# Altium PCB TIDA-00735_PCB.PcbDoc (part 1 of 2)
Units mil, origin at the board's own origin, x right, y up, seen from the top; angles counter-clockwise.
Board outline 1000 x 2200 mil, 2 copper layers (Top Layer, Bottom Layer), stack 62 mil thick; 69 components, 59 nets, 244 pads, 158 vias.
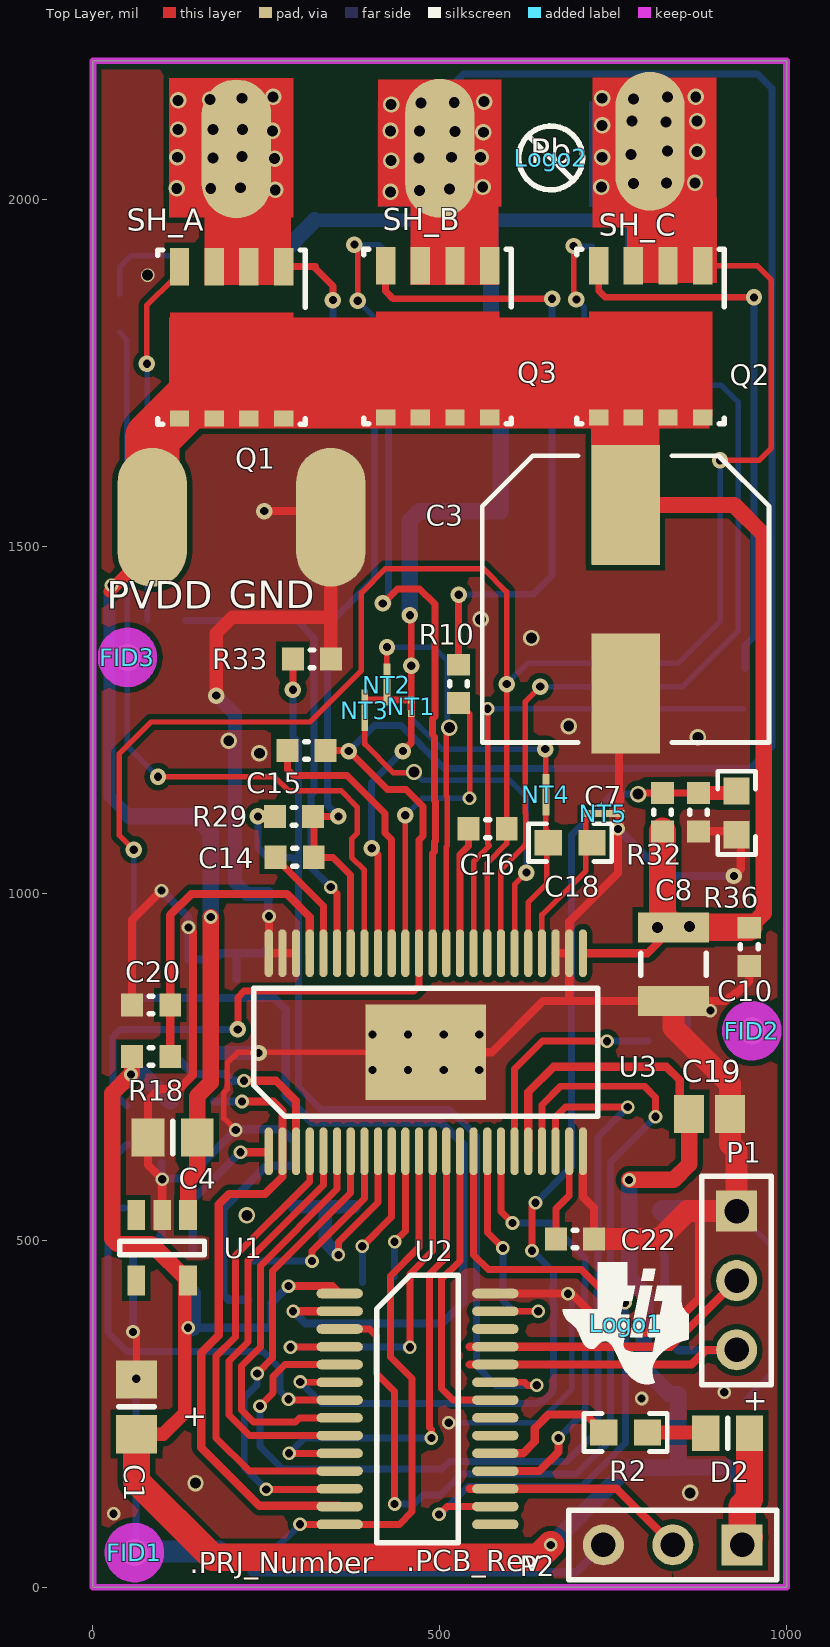
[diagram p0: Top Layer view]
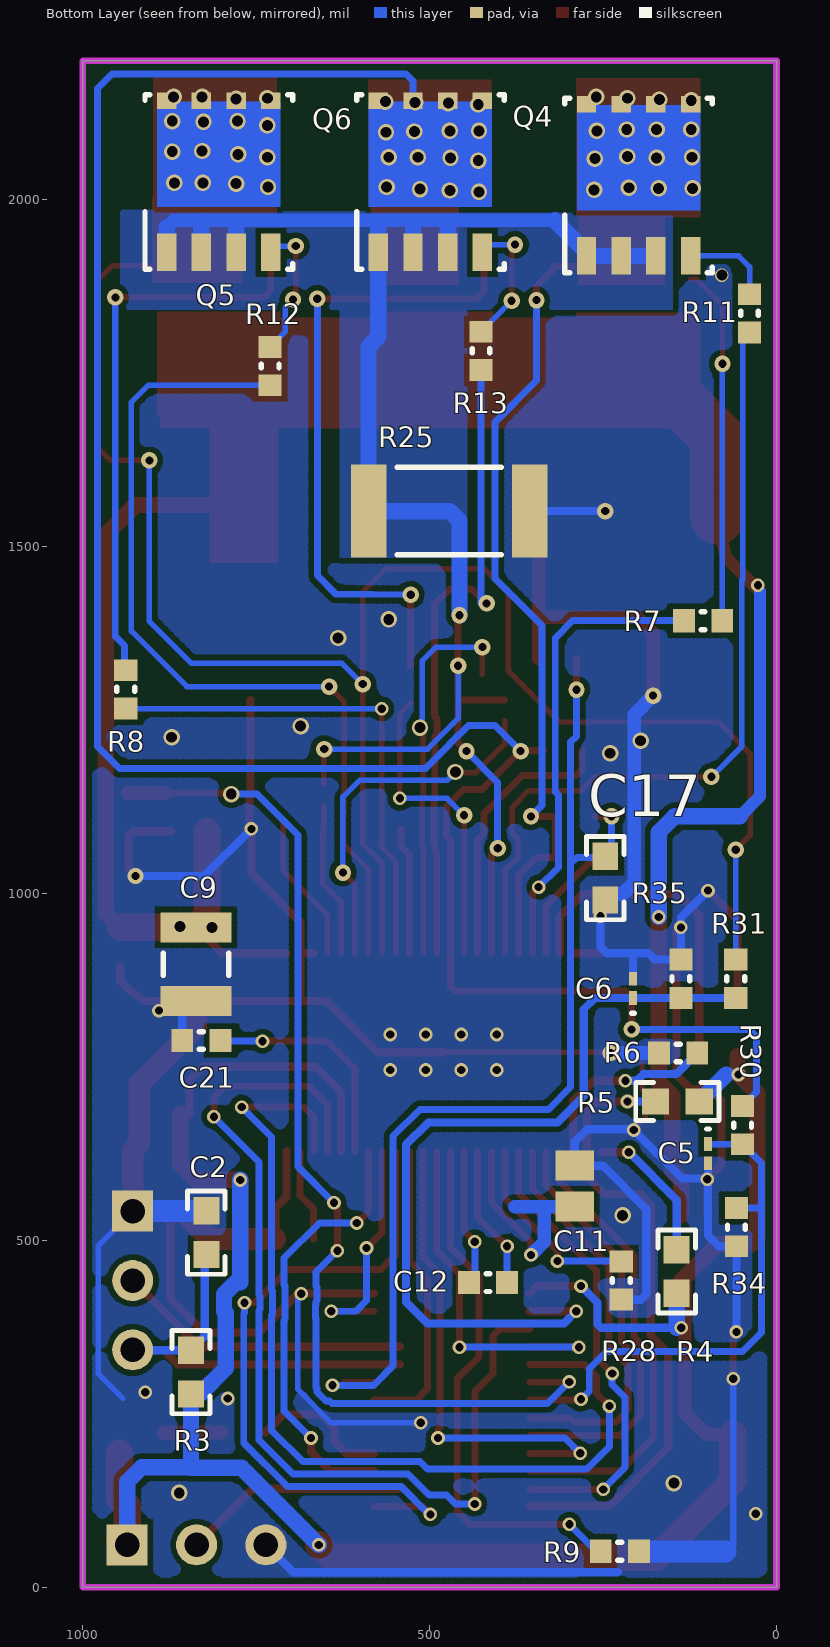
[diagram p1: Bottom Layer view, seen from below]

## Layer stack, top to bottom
Top Solder: solder mask 0.4, Solder Resist, Dk 3.5
Top Layer: signal copper 1.4
Dielectric1: core 59.2, FR-4, Dk 4.8
Bottom Layer: signal copper 1.4
Bottom Solder: solder mask 0.4, Solder Resist, Dk 3.5

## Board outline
0,0 1000,0 1000,2200 0,2200

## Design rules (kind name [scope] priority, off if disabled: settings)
AcuteAngle [All] p1: minimum=4.50000000000000E+0001 checktracksonly=FALSE
AssemblyTestPointUsage [All] p1: valid=2
Clearance Clearance_Keepouts [((IsTrack Or IsArc) And Not InPoly) And IsFree and IsKeepOut vs ((IsTrack Or IsArc) And Not InPoly) And IsFree and IsKeepOut] p1: gap=0
Clearance Clearance_BoardEdge_MountingHoles [OnCopper and InComponentClass('Mounting Holes') vs IsKeepOut] p2: gap=40
Clearance Clearance_BoardEdge_Poly [OnCopper and InPoly vs IsKeepOut] p3: gap=8
Clearance Clearance_BoardEdge [OnCopper and Not InComponentClass('Logo') and not InComponentClass('FiducialMark') and not InRegion(1000,500,4000,800) and Not IsKeepout vs IsKeepOut] p4: gap=8
Clearance Clearance_Poly [InPolygon] p5: gap=8
Clearance [All] p6: gap=7.87
ComponentClearance ComponentClearance_MountingHoles_FiducialMarks [InComponentClass('Mounting Holes') vs InComponentClass('FiducialMark')] p1: gap=50 collisioncheckmode=3 verticalgap=10 showdistances=FALSE
ComponentClearance ComponentClearance_Shunt [InComponentClass('Header') vs InComponentClass('Shunt')] p2: gap=0 collisioncheckmode=3 verticalgap=0 showdistances=FALSE
ComponentClearance ComponentClearance_Logo [InComponentClass('Logo')] p3: gap=50 collisioncheckmode=3 verticalgap=10 showdistances=FALSE
ComponentClearance ComponentClearance_ScrewToNut [(HasFootprint('NY PMS 440 0025 PH')) vs (HasFootprint('Keystone_1902C'))] p4: gap=5 collisioncheckmode=3 verticalgap=10 showdistances=FALSE
ComponentClearance ComponentClearance_MountingHoles [InComponentClass('Mounting Holes')] p5: gap=250 collisioncheckmode=3 verticalgap=100000 showdistances=FALSE
ComponentClearance ComponentClearance_SmallPassives [HasFootprint('0201*') or HasFootprint('0402*') or HasFootprint('0508') or HasFootprint('0603*') or HasFootprint('0612') or HasFootprint('0805*') or HasFootprint('0815*') or HasFootprint('0830*') or HasFootprint('1206*') or HasFootprint('1210*') or HasFootprint('1808*') or HasFootprint('1812*') or HasFootprint('1825*') or HasFootprint('2010*') or HasFootprint('2220*') or HasFootprint('2225*') or HasFootprint('2512*') or HasFootprint('2728*') or HasFootprint('3518*') vs HasFootprint('0201*') or HasFootprint('0402*') or HasFootprint('0508') or HasFootprint('0603*') or HasFootprint('0612') or HasFootprint('0805*') or HasFootprint('0815*') or HasFootprint('0830*') or HasFootprint('1206*') or HasFootprint('1210*') or HasFootprint('1808*') or HasFootprint('1812*') or HasFootprint('1825*') or HasFootprint('2010*') or HasFootprint('2220*') or HasFootprint('2225*') or HasFootprint('2512*') or HasFootprint('2728*') or HasFootprint('3518*')] p6: gap=8 collisioncheckmode=3 verticalgap=10 showdistances=FALSE
ComponentClearance ComponentClearance_THtoSMT [IsThruComponent vs IsSMTComponent] p7: gap=8 collisioncheckmode=3 verticalgap=30 showdistances=FALSE
ComponentClearance ComponentClearance_THtoTH [IsThruComponent vs IsThruComponent] p8: gap=118.11 collisioncheckmode=3 verticalgap=30 showdistances=FALSE
ComponentClearance [All] p9: gap=8 collisioncheckmode=3 verticalgap=10 showdistances=FALSE
DiffPairsRouting [All] p1: maxlimit=100 minlimit=10 mostfreqgap=10 toplayer_minwidth=15 toplayer_maxwidth=15 toplayer_prefwidth=15 bottomlayer_minwidth=15 bottomlayer_maxwidth=15 bottomlayer_prefwidth=15 maxuncoupledlength=1000
FabricationTestPointUsage TestPointUsage [All] p1: valid=2 allowmultiple=FALSE
FabricationTestpoint Testpoint [All] p1: side=3 testpointundercomponent=TRUE minsize=40 maxsize=100 preferedsize=60 minholesize=0 maxholesize=40 preferedholesize=32 testpointgrid=1 allowsidetop=TRUE allowsidebottom=TRUE usegrid=TRUE gridtolerance=0.01
FanoutControl Fanout_LCC [IsLCC] p1: bgadir=Out bgaviamode=Centered fanoutstyle=Auto fanoutdirection=Alternating viagrid=1 // Fanout_LCC (Default Rule)
FanoutControl Fanout_BGA [IsBGA] p2: bgadir=Out bgaviamode=Centered fanoutstyle=Auto fanoutdirection=Alternating viagrid=1 // Fanout_BGA (Default Rule)
FanoutControl Fanout_Default [All] p4: bgadir=Out bgaviamode=Centered fanoutstyle=Auto fanoutdirection=Alternating viagrid=1 // Fanout_Default (Default Rule)
FanoutControl Fanout_Small [(CompPinCount < 5)] p5: bgadir=Out bgaviamode=Centered fanoutstyle=Auto fanoutdirection=OutThenIn viagrid=1 // Fanout_Small (Default Rule)
HoleSize [All] p1: absolutevalues=TRUE maxlimit=251 minlimit=8 maxpercent=80.000 minpercent=20.000
MinimumAnnularRing MinimumAnnularRing_ThermalPadVias [IsVia and InAnyComponent] p1: minimumring=5.91
MinimumAnnularRing [All] p2: minimumring=9
MinimumSolderMaskSliver MinimumSolderMaskSliver_Logo [InComponentClass('Logo') vs InComponentClass('Logo')] p1: minsoldermaskwidth=0.7
MinimumSolderMaskSliver [All] p2: minsoldermaskwidth=3.94
PlaneConnect [All] p1: planeconnectstyle=Direct reliefexpansion=10 reliefentries=4 reliefconductorwidth=10 reliefairgap=10
PolygonConnect [All] p1: connectstyle=Direct reliefconductorwidth=10 reliefentries=4 polygonreliefangle="90 Angle" airgapwidth=10
RoutingVias ThermalPadVias [IsVia and InAnyComponent] p1: holewidth=7.87 width=19.68 viastyle="Through Hole" minholewidth=7.87 minwidth=19.68 maxholewidth=12.99 maxwidth=23.62
RoutingVias [All] p2: holewidth=16 width=34 viastyle="Through Hole" minholewidth=7.87 minwidth=19 maxholewidth=40 maxwidth=65
SilkToBoardRegionClearance [Not ((IsComment or IsDesignator) And (Hide <> 'False')) and not InRegion(1000,500,4000,800)] p1:
SilkToSilkClearance SilkToSilkClearance_Pb-FreeLogo [(HasFootprint('Pb-Free_Overlay_Medium') OR HasFootprint('Pb-Free_Overlay_Small')) vs (HasFootprint('Pb-Free_Overlay_Medium') OR HasFootprint('Pb-Free_Overlay_Small'))] p1: silktosilkclearance=0
SilkToSilkClearance [All] p2: silktosilkclearance=4
SilkToSolderMaskClearance SilkToComonentPadClearance [IsPad and InAnycomponent] p1: minsilkscreentomaskgap=5 clearancetoexposedcopper=TRUE
SilkToSolderMaskClearance "Silk to Solder Mask Opening" [All] p2: minsilkscreentomaskgap=4 clearancetoexposedcopper=FALSE
SolderMaskExpansion [All] p1: expansion=1.97
UnpouredPolygon [All] p1: allowunpoured=FALSE
Width [All] p1: maxlimit=100 minlimit=6 preferedwidth=10 checkconnectedcopper=TRUE
14 further rules are at their usual default settings.

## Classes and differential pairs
component class Logo: Logo1
component class TIDA-00735_Hardware: FID1 FID2 FID3 Logo1 Logo2 ZZ2 ZZ3 ZZ4
component class FiducialMark: FID1 FID2 FID3
component class AssemblyNote: ZZ2 ZZ3 ZZ4
component class TIDA-00735_DRV8303: C3 C5 C6 C7 C8 C9 C10 C11 C12 C14 C15 C16 C17 C18 C20 C21 C22 NT1 NT2 NT3 NT4 NT5 Q1 Q2 Q3 Q4 Q5 Q6 R4 R5 R6 R7 R8 R9 R10 R11 R12 R13 R18 R25 R28 R29 R30 R31 R32 R33 R34 R35 R36 U3
component class TIDA-00735_MCU: C1 C2 C4 C19 D2 P1 P2 R2 R3 U1 U2

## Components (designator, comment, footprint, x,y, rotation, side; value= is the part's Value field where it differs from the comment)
C1 "CAP" 6-0805_M 63,260 r90 top
C2 "CAP" 0603#1 822,511 r90 bottom
C3 "CAP 470uF" CAPAE1030X1080 768,1424 r270 top
C4 "CAP" 6-0805_N 115,648 r180 top
C5 "C0603C102J5GAC" 0603#2 99,625 r270 bottom
C6 "C0603C102J5GAC" 0603#2 207,863 r90 bottom
C7 "C0603C102J5GAC" 0603#1 928,1116 r270 top
C8 "GRM32ER72A225KA35L" 1210L 837,898 r270 top
C9 "GRM32ER72A225KA35L" 1210L 837,898 r270 bottom
C10 "GRM188R72A104KA35D" 0603L 946,923 r270 top
C11 "GRM219R61E225KA12D" 0805L 291,578 r90 bottom
C12 "C1608X7R1H223K" 0603L 416,439 r0 bottom
C14 "C1608X7R1H104K" 0603L 291,1052 r0 top
C15 "C1608X7R1H104K" 0603L 308,1206 r0 top
C16 "C1608X7R1H104K" 0603L 569,1093 r0 top
C17 "C0603C102J5GAC" 0603#1 247,1022 r270 bottom
C18 "C0603C102J5GAC" 0603#1 688,1073 r0 top
C19 "GRM219R61E225KA12D" 0805L 889,682 r180 top
C20 "C1608X7R1E104K" 0603L 84,839 r180 top
C21 "GRM188R61E105KA12D" 0603L 829,788 r0 bottom
C22 "GRM188R61E105KA12D" 0603L 695,502 r0 top
D2 "LED1" 6-0805_L 915,222 r180 top
FID1 "Fiducial" Fiducial10-20 60,50 r0 top
FID2 "Fiducial" Fiducial10-20 950,802 r0 top
FID3 "Fiducial" Fiducial10-20 50,1340 r0 top
Logo1 "Texas Instruments" TI_Symbol_Overlay_Small 768,380 r0 top
Logo2 "Pb-Free Symbol" Pb-Free_Overlay_Small 660,2060 r0 top
NT1 "Net-Tie" Net-Tie_10mil 459,1269 r270 top net-tie
NT2 "Net-Tie" Net-Tie_10milWide_30milLong 424,1301 r90 top net-tie
NT3 "Net-Tie" Net-Tie_10milWide_30milLong 392,1264 r270 top net-tie
NT4 "Net-Tie" Net-Tie_10milWide_30milLong 653,1142 r90 top net-tie
NT5 "Net-Tie" Net-Tie_10milWide_30milLong 736,1115 r0 top net-tie
P1 "Header 3" HDR1X3 928,542 r270 top
P2 "Header 3" HDR1X3 936,61 r180 top
Q1 "CSD17573Q5B" TRANS_NexFET_Q5B 200,1794 r270 top
Q2 "CSD17573Q5B" TRANS_NexFET_Q5B 804,1795 r270 top
Q3 "CSD17573Q5B" TRANS_NexFET_Q5B 497,1795 r270 top
Q4 "CSD17573Q5B" TRANS_NexFET_Q5B 199,2028 r90 bottom
Q5 "CSD17573Q5B" TRANS_NexFET_Q5B 804,2033 r90 bottom
Q6 "CSD17573Q5B" TRANS_NexFET_Q5B 499,2033 r90 bottom
R2 "RES" 0603#1 768,223 r180 top
R3 "RES" 0603#1 844,310 r270 bottom
R4 "CRCW06033K30JNEA" 0603#1 144,455 r270 bottom
R5 "CRCW06033K30JNEA" 0603#1 143,700 r0 bottom
R6 "CRCW06031R00JNEA" 0603L 142,770 r180 bottom
R7 "CRCW060310R0JNEA" 0603L 106,1393 r180 bottom
R8 "CRCW060310R0JNEA" 0603L 938,1294 r90 bottom
R9 "CRCW06031K00JNEA" 0603L 226,52 r0 bottom
R10 "CRCW060310R0JNEA" 0603L 527,1302 r90 top
R11 "CRCW060310R0JNEA" 0603L 39,1836 r90 bottom
R12 "CRCW060310R0JNEA" 0603L 730,1760 r90 bottom
R13 "CRCW060310R0JNEA" 0603L 426,1782 r90 bottom
R18 "CRCW06030000Z0EA" 0603L 84,765 r180 top
R25 "HCJ2512ZT0R00" 2512 472,1551 r0 bottom
R28 "CRCW06031K00JNEA" 0603L 224,442 r90 bottom
R29 "CRCW060310R0JNEA" 0603L 290,1111 r0 top
R30 "CRCW060310R0JNEA" 0603L 49,666 r90 bottom
R31 "CRCW060310R0JNEA" 0603L 59,877 r90 bottom
R32 "CRCW060310R0JNEA" 0603L 821,1117 r270 top
R33 "CRCW060310R0JNEA" 0603L 316,1338 r180 top
R34 "CRCW060310R0JNEA" 0603L 58,519 r90 bottom
R35 "CRCW060310R0JNEA" 0603L 138,877 r270 bottom
R36 "CRCW060310R0JNEA" 0603L 873,1117 r90 top
U1 "TPS70933" DBV0005A_N 100,489 r270 top
U2 "MSP430G2553IPW28" PW0028A_N 468,257 r0 top
U3 "DRV8303DCA" DCA0048A_N 480,771 r90 top locked
ZZ2 "These assemblies are ESD sensitive, ESD precautions shall be observed." AssemblyNote 185,3829.11 r0 top
ZZ3 "These assemblies must be clean and free from flux and all contaminants. Use of no clean flux is not acceptable." AssemblyNote 185,3740.56 r0 top
ZZ4 "These assemblies must comply with workmanship standards IPC-A-610 Class 2, unless otherwise specified." AssemblyNote 185,3652 r0 top

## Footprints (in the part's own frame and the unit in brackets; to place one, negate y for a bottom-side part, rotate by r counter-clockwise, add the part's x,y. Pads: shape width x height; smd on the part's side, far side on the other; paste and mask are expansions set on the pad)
6-0805_L [mm] "Chip Resistor, Body 2.0x1.2mm, IPC High Density"
  rect 1x1.3 smd: 1(-0.8,0) 2(0.8,0)
  silkscreen extent 0,-0.55 0,0.55, body extent -1.07,-0.7 1.07,0.7, height 0.7
6-0805_M [mm] "Chip Resistor, Body 2.0x1.2mm, IPC Low Density"
  rect 1.4x1.5 smd: 1(-1,0) 2(1,0)
  silkscreen extent 0,-0.65 0,0.65, body extent -1.07,-0.7 1.07,0.7, height 0.7
6-0805_N [mm] "Chip Resistor, Body 2.0x1.2mm, IPC Medium Density"
  rect 1.2x1.4 smd: 1(-0.9,0) 2(0.9,0)
  silkscreen extent 0,-0.6 0,0.6, body extent -1.07,-0.7 1.07,0.7, height 0.7
0603#1 [mm] "0603 from SM-752 data"
  rect 1x0.95 smd: 1(-0.8,0) 2(0.8,0)
  silkscreen extent -1.52,-0.69 1.52,0.69, body extent -0.87,-0.47 0.87,0.47, height 0.85
0603#2 [mm] "Chip Inductor, Body 0.6x0.3mm, IPC High Density"
  rect 0.5x0.3 smd: 1(-0.35,0) 2(0.35,0)
  silkscreen extent -0.9,-0.05 -0.9,0.05, body extent -0.33,-0.18 0.33,0.18, height 0.55
0603L [mm]
  rect 0.8x0.85 smd: 1(-0.7,0) 2(0.7,0)
  silkscreen extent -0.07,-0.33 0.07,0.33, body extent -0.87,-0.47 0.87,0.47, height 0.85
0805L [mm]
  rect 1.1x1.4 smd: 1(-0.75,0) 2(0.75,0)
  body extent -1.1,-0.72 1.1,0.72, height 1.1
1210L [mm]
  rect 1.1x2.6 smd: 1(-1.35,0) 2(1.35,0)
  silkscreen extent -0.4,-1.2 0.4,1.2, body extent -1.7,-1.35 1.7,1.35, height 1.35
2512 [mm] "Chip Resistor, Body 6.3x3.2mm, IPC Medium Density"
  rect 1.3x3.4 smd: 1(-2.95,0) 2(2.95,0)
  silkscreen extent -1.9,-1.6 1.9,1.6, body extent -3.22,-1.67 3.22,1.67, height 0.71
AssemblyNote [mil] "Assembly Note"
CAPAE1030X1080 [mm] "10.3 x 10.3 mm base"
  rect 4.4x2.5 smd: 1(-3.45,0) 2(3.45,0)
  silkscreen extent -5.25,-5.25 5.25,5.25, body extent -5.26,-5.26 5.26,5.26, height 10.5
DBV0005A_N [mm] "SOT23, 5-Leads, Body 2.9x1.6mm, Pitch 0.95mm, Lead Span 2.8mm, IPC Medium Density"
  rect 1.1x0.65 smd: 1(-1.2,0.95) 2(-1.2,0) 3(-1.2,-0.95) 4(1.2,-0.95) 5(1.2,0.95)
  silkscreen extent -0.25,-1.55 0.25,1.55, body extent -1.42,-1.46 1.42,1.46, height 1.08
DCA0048A_N [mm] "TSSOP, 48-Leads, Body 12.6x6.2mm (max), Pitch 0.50mm, IPC Medium Density"
  oval 1.75x0.3 smd: 1(-3.625,5.75) 2(-3.625,5.25) 3(-3.625,4.75) 4(-3.625,4.25) 5(-3.625,3.75) 6(-3.625,3.25) 7(-3.625,2.75) 8(-3.625,2.25) 9(-3.625,1.75) 10(-3.625,1.25) 11(-3.625,0.75) 12(-3.625,0.25) 13(-3.625,-0.25) 14(-3.625,-0.75) 15(-3.625,-1.25) 16(-3.625,-1.75) 17(-3.625,-2.25) 18(-3.625,-2.75) 19(-3.625,-3.25) 20(-3.625,-3.75) 21(-3.625,-4.25) 22(-3.625,-4.75) 23(-3.625,-5.25) 24(-3.625,-5.75) 25(3.625,-5.75) 26(3.625,-5.25) 27(3.625,-4.75) 28(3.625,-4.25) 29(3.625,-3.75) 30(3.625,-3.25) 31(3.625,-2.75) 32(3.625,-2.25) 33(3.625,-1.75) 34(3.625,-1.25) 35(3.625,-0.75) 36(3.625,-0.25) 37(3.625,0.25) 38(3.625,0.75) 39(3.625,1.25) 40(3.625,1.75) 41(3.625,2.25) 42(3.625,2.75) 43(3.625,3.25) 44(3.625,3.75) 45(3.625,4.25) 46(3.625,4.75) 47(3.625,5.25) 48(3.625,5.75)
  rect 3.48x4.42 smd: 49(0,0)
  silkscreen extent -2.35,-6.3 2.35,6.3, body extent -4.06,-6.25 4.06,6.25, height 0.98
Fiducial10-20 [mm]
  round 1 smd mask+0.5: 1(0,0)
  Top Layer keep-out circle w1.178: c0,0 r0.5
HDR1X3 [mm] "Connector; Header; 3 Position"
  rect 1.5x1.5 hole 0.9: 1(0,0)
  round 1.5 hole 0.9: 2(2.54,0) 3(5.08,0)
  silkscreen extent -1.27,-1.27 6.35,1.27
Net-Tie_10mil [mil] "10mil net tie, no solder mask opening, no solder paste"
  rect 10x10 smd paste-5 mask-5: 1(-10,0) 2(10,0)
  Top Layer region: -6,5 6,5 6,-5 -6,-5
Net-Tie_10milWide_30milLong [mil] "10mil net tie, no solder mask opening, no solder paste"
  rect 30x10 smd paste-5 mask-5: 1(-15,0) 2(15,0)
Pb-Free_Overlay_Small [mil]
  silkscreen extent -46,-46 46,46
PW0028A_N [mm] "TSOP, 28-Leads, Body 9.7x4.4mm, Pitch 0.65mm, IPC Medium Density"
  oval 1.7x0.35 smd: 1(-2.85,4.225) 2(-2.85,3.575) 3(-2.85,2.925) 4(-2.85,2.275) 5(-2.85,1.625) 6(-2.85,0.975) 7(-2.85,0.325) 8(-2.85,-0.325) 9(-2.85,-0.975) 10(-2.85,-1.625) 11(-2.85,-2.275) 12(-2.85,-2.925) 13(-2.85,-3.575) 14(-2.85,-4.225) 15(2.85,-4.225) 16(2.85,-3.575) 17(2.85,-2.925) 18(2.85,-2.275) 19(2.85,-1.625) 20(2.85,-0.975) 21(2.85,-0.325) 22(2.85,0.325) 23(2.85,0.975) 24(2.85,1.625) 25(2.85,2.275) 26(2.85,2.925) 27(2.85,3.575) 28(2.85,4.225)
  silkscreen extent -1.5,-4.9 1.5,4.9, body extent -3.21,-4.85 3.21,4.85, height 0.98
TI_Symbol_Overlay_Small [mil]
  silkscreen extent -90,-88 91,88
TRANS_NexFET_Q5B [mm] "TI recommended land pattern (nominal) November 2012"
  rect 1.372x0.71 smd paste-0.4: 1(-2.776,1.905) 2(-2.776,0.635) 3(-2.776,-0.635) 4(-2.776,-1.905)
  rect 0.59x0.71 smd paste-0.3: 5(2.776,-1.905) 6(2.776,-0.635) 7(2.776,0.635) 8(2.776,1.905)
  Top Layer region: -1.106,-2.26 2.744,-2.26 2.744,2.26 -1.106,2.26
  silkscreen extent -3.38,-2.7 3,2.7, body extent -3.23,-2.55 2.87,2.55, height 1.06

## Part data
C1 C2 C4: library part C0603C105K8PACTU
C3: library part CAP_33OSR100-14315EC, "Capacitor, Aluminum, 50VDC, -10+20%"
C5 C6 C7 C17 C18: "CAP, CERM, 1000pF, 50V, +/-5%, C0G/NP0, 0603"
C8 C9: "CAP, CERM, 2.2uF, 100V, +/-10%, X7R, 1210"
C10: "CAP, CERM, 0.1uF, 100V, +/-10%, X7R, 0603"
C11: "CAP, CERM, 2.2uF, 25V, +/-10%, X5R, 0805"
C12: "CAP, CERM, 0.022uF, 50V, +/-10%, X7R, 0603"
C14 C15 C16: "CAP, CERM, 0.1uF, 50V, +/-10%, X7R, 0603"
C19: "CAP, CERM, 1uF, 25V, +/-10%, X5R, 0805"
C20: "CAP, CERM, 0.1uF, 25V, +/-10%, X7R, 0603"
C21 C22: "CAP, CERM, 1uF, 25V, +/-10%, X5R, 0603"
D2: library part LED2, "Typical RED, GREEN, YELLOW, AMBER GaAs LED"
FID1 FID2 FID3: "Fiducial mark.  There is nothing to buy or mount."
Logo1: library part TI_Logo, "Texas Instrument Corporate Signature"
Logo2: library part Pb-Free
NT1 NT2 NT3 NT4 NT5: "Single point connection between nets."
P1 P2: "Header, 3-Pin"
Q1 Q2 Q3 Q4 Q5 Q6: "MOSFET, N-CH, 30 V, 100 A, SON 5x6mm"
R2 R3: library part CRCW060330K0JNEA
R4 R5: "RES, 3.3 k, 5%, 0.1 W, 0603"
R6: "RES, 1.0 ohm, 5%, 0.1W, 0603"
R7 R8 R10 R11 R12 R13 R29 R30 R31 R32 R33 R34 R35 R36: "RES, 10 ohm, 5%, 0.1W, 0603"
R9 R28: "RES, 1.0k ohm, 5%, 0.1W, 0603"
R18: "RES, 0 ohm, 5%, 0.1W, 0603"
R25: library part ERJ-M1WSF5M0U, "RES, 5 mohm, 63.2A JUMP, 2512"
U1: library part TPS709
U2: "Mixed Signal Microcontroller, PW0028A"
U3: "THREE PHASE PRE-DRIVER WITH DUAL CURRENT SHUNT AMPLIFIERS, DCA0048A"
ZZ2 ZZ3 ZZ4: library part AssemblyNote

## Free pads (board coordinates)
  oval 100x200 smd: 0(85.57,1542) 1(343,1542) 2(207,2073) 3(500,2074) 4(803,2084)

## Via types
v1: diameter 23.62, hole 15.75, Top Layer to Bottom Layer, 62 vias
v2: diameter 19.68, hole 11.81, Top Layer to Bottom Layer, 55 vias
v3: diameter 23.62, hole 11.81, Top Layer to Bottom Layer, 26 vias
v4: diameter 19.68, hole 12, Top Layer to Bottom Layer, 8 vias
v5: diameter 23.62, hole 11.81, Top Layer to Bottom Layer, tented both sides, 6 vias
v6: diameter 19.68, hole 15.75, Top Layer to Bottom Layer, 1 vias

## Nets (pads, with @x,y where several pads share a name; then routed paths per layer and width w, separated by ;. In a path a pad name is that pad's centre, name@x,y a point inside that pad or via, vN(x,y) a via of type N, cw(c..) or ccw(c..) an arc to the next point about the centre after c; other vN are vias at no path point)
+3.3V: C1.1 C19.2 D2.1 P2.1 R3.2 R4.2 R5.1 R18.2 U1.5 U2.1 U3.20 | length 3361.8
  Top Layer w11.81: v2(282,434) 345.13,434 U2.1@355.79,423.34 ; U3.20@627.64,628.28 627.64,713.64 664,750 827,750 846,731 C19.2@846,681.47
  Top Layer w19.68: C1.1@63,220.63 101.63,220.63 132.6,251.6 132.6,436.95 U1.5@137.4,441.76
  Top Layer w23.62: R18.2@56.44,765 56.44,740.44 v2(55,739) 28,712 28,502 35.31,494.69 84.47,494.69 U1.5@137.4,441.76 ; v2(773,587) 837,587 859.47,609.47 C19.2@859.47,682
  Top Layer w39.37: C1.1@63,220.63 63,153 173,43 594,43 ; 614,43 594,43 ; v2(660,61) 642,43 594,43 ; P2.1@946.5,71.5 P2.1@936,61 936,116.5 946.5,127 946.5,193
  Bottom Layer w11.81: v2@144,374 253,374 258,379 258,410 v2(282,434)
  Bottom Layer w23.62: 72.5,739 R5.1@111.5,700 ; v2@144,374 R4.2@144,423.5 ; v2(660,61) 771,172 845,172 844,173 ; v2(773,587) 773,439.53 779.23,439.53 796.53,422.23 796.53,397.77 793.94,395.19 793.94,315.56 831,278.5 R3.2@844,278.5 844,173 ; P2.1@936,61 936,152 915,173 844,173
  other v2: 137.4,374
+PVDD: C3.1 C4.1 C8.1 C9.1 C10.1 pad.0 Q1.5 Q1.6 Q1.7 Q1.8 Q2.5 Q2.6 Q2.7 Q2.8 Q3.5 Q3.6 Q3.7 Q3.8 R32.2 U1.1 U3.25 | length 2559.1
  Top Layer w11.81: U3.25@706.38,913.72 799.57,913.72 C8.1@837,951.15
  Top Layer w17.72: v2@24,1435 73,1484 pad.0@85.57,1542
  Top Layer w23.62: U1.1@137.4,536.24 137.4,587 150.43,600.03 C4.1@150.43,648 150.43,707.83 170,727.4 v2(170,966) ; C3.1@768,1559.83 924.17,1559.83 967,1517 967,971.56 C10.1@946,950.56
  Top Layer w39.37: R32.2@821,1089.44 821,967.15 C8.1@837,951.15 C10.1@945.41,951.15
  Top Layer w78.74: pad.0@85.57,1542 85.57,1656.57 154,1725
  Bottom Layer w17.72: v2@24,1435 24,1140 53,1111
  Bottom Layer w23.62: 53,1111 147,1111 170,1088 v2(170,966)
  other v1: 814,951 860,952
  other v2: 27,1444
\OCTW: R4.1 U3.1 | length 208.4
  Top Layer w11.81: v2(213,627) U3.1@252.34,627
  Bottom Layer w11.81: R4.1@144,486.5 144,558 v2(213,627)
A_ISENSE_N: C18.2 NT5.1 U3.28 | length 231.8
  Top Layer w7.87: U3.28@647.32,913.72 647.32,969 710.78,1032.46 710.78,1104.78 NT5.1@721,1115
A_ISENSE_P: C18.1 NT4.1 U3.29 | length 235.7
  Top Layer w7.87: U3.29@627.64,913.72 627.64,987.28 654,1013.64 C18.1@654,1091 ; C18.1@652.5,1079 NT4.1@652.5,1126.5
ADC_PHA: C17.1 R29.1 R33.2 U2.23 | length 1535.2
  Top Layer w10: v3(238,1111) R29.1@262.44,1111 ; v3(288.44,1293.44) R33.2@288.44,1338 ; U2.23@580.2,295.39 622,295.39 626.39,291 v2(640,291)
  Bottom Layer w10: v3(238,1111) 238,1065.78 251.78,1052 287.78,1052 296.78,1043 ; v3(288.44,1293.44) 288.44,1226.34 296.78,1218 296.78,1043 ; v2(640,291) 581,291 552.78,319.22 552.78,650.22 514.22,688.78 329,688.78 296.78,721 296.78,1043
ADC_PHB: C5.1 R30.1 R34.2 U2.7 | length 758.6
  Top Layer w10: v2(282,271) 283.2,269.8 U2.7@355.79,269.8
  Bottom Layer w10: 24.44,546.56 R34.2@58,546.56 ; C5.1@98.66,638.44 R30.1@49,638.44 22,611.44 22,367 49,340 245,340 270,315 270,283 v2(282,271)
ADC_PHC: C6.1 R31.1 R35.2 U2.2 | length 1195.3
  Top Layer w11.81: v2(288.75,397.75) U2.2@355.79,397.75
  Bottom Layer w11.81: R31.1@59,849.44 261.56,849.44 278,833 278,708 316,670 502,670 534,638 534,411 503,380 306.5,380 v2(288.75,397.75)
ADC_VBUS: C7.1 R32.1 R36.2 U2.6 | length 1548.7
  Top Layer w10: v2@299.61,295.39 U2.6@355.79,295.39 ; v2(633,485) 633,549 v2(638,554) ; v1@787.56,1144.56 R32.1@821,1144.56 R36.2@880.78,1144.56
  Top Layer w19.68: R36.2@881,1144.78 C7.1@935,1144.78
  Bottom Layer w10: v2(299,296) 330,265 641,265 644.28,268.28 649.41,268.28 662.72,281.59 662.72,286.72 664,288 664,387.62 664.72,388.34 664.72,407.16 664,407.87 664,411.87 662.28,413.59 662.28,432.41 664,434.13 664,454 v2(633,485) ; v2(638,554) 690,606 690,1084 749,1143 v1(786,1143)
COM: P2.2 U2.17 | length 326.3
  Top Layer w11.81: 543.2,141.84 U2.17@580.2,141.84 753.16,141.84 755.16,141.84 P2.2@836,61
DC_CAL: R28.2 U3.8 | length 281.1
  Top Layer w10: v2(316,470) 316,484.58 391.42,560 U3.8@391.42,628.28
  Bottom Layer w10: R28.2@224.44,470 v2(316,470)
DVDD: C21.1 U3.19 | length 329.7
  Top Layer w10: U3.19@607.95,628.28 607.95,746.95 648,787 v2(741,787) v2@741,789
  Bottom Layer w10: v2(741,787) C21.1@800.44,787
EN_GATE: R9.2 U2.14 U3.12 | length 779.7
  Top Layer w10: v2(298.66,90.66) U2.14@355.79,90.66 441.98,90.66 460.31,109 460.31,300.69 429,332 429,448.84 470.16,490 U3.12@470.16,628.28
  Bottom Layer w10: R9.2@253.56,52 260,52 v2(298.66,90.66)
FAULT: R5.2 U2.13 U3.2 | length 903.4
  Top Layer w11.81: v2(215,700) 260,700 273.31,686.69 U3.2@273.31,628.28 273.31,591.59 248.31,566.59 196.4,566.59 181.41,551.6 181.41,363.03 156.22,337.84 156.22,201.37 240.22,117.38 354.67,117.38 U2.13@355.79,116.25
  Bottom Layer w11.81: R5.2@174.5,700 v2(215,700)
GH_A: R7.1 U3.43 | length 667.4
  Top Layer w10: v2(343,1009) 352.05,999.95 U3.43@352.05,913.72
  Bottom Layer w10: R7.1@133.56,1393 294,1393 319,1368 319,1146 314.65,1141.65 314.65,1037.35 v2(343,1009)
GH_B: R10.1 U3.38 | length 446.1
  Top Layer w7.87: U3.38@450.47,913.72 v3(450.47,1112.47) ; R10.1@527,1275 543,1259 v2(543,1137)
  Bottom Layer w7.87: v3(450.47,1112.47) 475,1137 v2(543,1137)
GH_C: R8.1 U3.33 | length 731.3
  Top Layer w7.87: U3.33@548.9,913.72 548.9,1045.9 552.83,1049.84 552.83,1050.11 571.55,1068.82 569,1071.38 569,1114.62 ; 569,1114.63 v2(569,1266)
  Bottom Layer w7.87: v2(569,1266) R8.1@937.56,1266
GL_A: R11.1 U3.41 | length 1189.9
  Top Layer w7.87: v3(94,1168) 262,1168 282,1148 357.42,1148 381,1124.42 381,1086.58 373,1078.58 373,1052 391.42,1033.58 U3.41@391.42,913.72
  Bottom Layer w7.87: R11.1@39,1808.44 48.87,1798.58 48.87,1452.07 49.94,1451 49.94,1212.06 v3(94,1168)
GL_B: R13.1 U3.36 | length 937.7
  Top Layer w10: v3(418,1418) 439,1439 471,1439 493.09,1416.91 493.09,1255 489.31,1251.23 489.31,1228.78 492.72,1225.37 492.72,1133.56 493.87,1132.4 493.87,1075.6 492.72,1074.44 492.72,1060.63 489.84,1057.76 U3.36@489.84,913.72
  Bottom Layer w10: v3@426,1418 R13.1@426,1754.44
GL_C: R12.1 U3.31 | length 1266.7
  Top Layer w7.87: U3.31@588.27,913.72 588.27,1034.55 623.33,1069.61 623.33,1070.59 624.12,1071.38 624.12,1114.62 623.33,1115.41 623.33,1276.33 v3(645,1298)
  Bottom Layer w7.87: v3(645,1298) 850,1298 930,1378 930,1708 905.56,1732.44 R12.1@730,1732.44
GND: C1.2 C2.2 C3.2 C4.2 C5.2 C6.2 C7.2 C8.2 C9.2 C10.2 C11.2 C17.2 C19.1 C20.2 C21.2 C22.2 NT5.2 P1.1 P2.3 pad.1 R6.1 R9.1 R25.1 R28.1 R33.1 R34.1 R35.1 R36.1 U1.2 U2.28 U3.24 U3.26 U3.27 U3.46 U3.47 U3.48 U3.49 | length 7689.7
  Top Layer w7.87: v2(206,659) 189,676 189,712.99 194,717.99 194,756 209,771 v3@239,771 ; v3@240,771 U3.49@480,771
  Top Layer w10: v2(58,368) 63,363 C1.2@63,299.37
  Top Layer w11.81: C20.2@56.44,839 56.44,961.44 v2(99,1004) ; U1.2@100,536.24 v2(100,588) 79.57,608.43 C4.2@79.57,648 79.57,701.57 96,718 124.41,718 144.41,738 v2@144.41,944.59 ; v3(247,1551) 334,1551 pad.1@343,1542 ; v2(254,967) 254,914.1 U3.48@253.62,913.72 U3.47@273.31,913.72 U3.46@292.99,913.72 ; U3.49@480,771 575.15,771 649,844.85 C8.2@837,844.85 911.87,844.85 918.61,851.59 921.37,851.59 927.09,857.31 929.31,857.31 946,874 C10.2@946,895.44 ; U2.28@580.2,423.34 689.66,423.34 746,367 825.16,367 874,415.84 874,542 ; U3.27@667.01,913.72 U3.26@686.69,913.72 ; 686.69,848.31 U3.26@686.69,913.72 ; U3.24@706.38,628.28 706.38,562.62 722.56,546.44 C22.2@722.56,502 ; 758.43,1143 C3.2@758.43,1278.61 ; 759.61,1143 759.61,1095.61 v2(757,1093) 757,1029.31 686.69,959 U3.26@686.69,913.72 ; R36.1@873,1089.44 C7.2@927,1089.44 ; v3(924,1025) 934,1035 934,1082.44 C7.2@926.44,1090
  Top Layer w19.68: v3(178,1285) 178,1375 201,1398 343,1398 ; v3(239,770) v3@240,770 ; R33.1@343,1338.56 343,1398 ; pad.1@343,1542 343,1398
  Top Layer w31.5: C22.2@722.56,502 817,502 857,542 874,542 P1.1@928,542 928,629 918.53,638.47 C19.1@918.53,682 918.53,725.05 837,806.58 C8.2@837,844.85
  Bottom Layer w7.87: v2(206,659) v2@206,660 ; v2(513,237) 642,237 690,285 690,422 689,423 v2(685,423) ; P1.1@928,542 978,492 978,308 942,272
  Bottom Layer w10: v2(62.5,300.5) 62.5,62.5 73,52
  Bottom Layer w11.81: v2(58,368) R34.1@58,491.44 83.44,491.44 99,507 v2@99,588 ; 73,52 73.5,51.5 ; v2@99,589 C5.2@99,611.22 ; v2(99,1004) 138,965 v2(138,951) R35.1@138,904.56 175.56,904.56 184.72,913.72 244.72,913.72 254,923 v2(254,967) ; v2@100,589 136,589 v2(206,659) ; v2@206,660 273,660 291,642 C11.2@291,607.53 250.53,607.53 188,545 188,422 195.56,414.44 R28.1@224,414.44 ; C6.2@207,876.78 207,909.43 ; 228.95,21.49 696.49,21.49 P2.3@736,61 ; v3(247,1551) R25.1@355.86,1551 ; v2@253,968 C17.2@253,999 ; v2(757,1093) 825,1025 v3@926,1025 ; C9.2@837,844.85 855.85,826 860.92,831.07 v2(890.15,831.07) ; C21.2@856.56,788 C9.2@856.56,825.29
  Bottom Layer w19.68: R6.1@169.56,770 v3(239,770) ; v3(178,1285) 205,1258 205,1016 222,999 C17.2@253,999
  Bottom Layer w31.5: 73.5,51.5 181,51.5 ; C2.2@822,542.5 822.5,542 P1.1@928,542
  other v1: 861,136 148,150 222,536 240,1202 196,1220 872,1225 686,1241 632,1368 559,1395
  other v2: 30,106 791,272 910,281
  other v4: 403.23,745.41 454.41,745.41 505.59,745.41 556.77,745.41 403.23,796.59 454.41,796.59 505.59,796.59 556.77,796.59
  other v6: 79,1891
IA_FB: U2.3 U3.21 | length 1429.9
  Top Layer w10: U2.3@355.79,372.16 398.84,372.16 409,362 409,308 435,282 v2(435,120) ; U3.21@647.32,628.28 647.32,695.32 674,722 795,722 811,706 v2(811,678)
  Bottom Layer w10: v2(435,120) 463,120 476,133 501,133 531.13,163.13 696.87,163.13 746,212.25 746,398.87 744.28,400.59 744.28,419.41 746,421.13 746,613 v2(811,678)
